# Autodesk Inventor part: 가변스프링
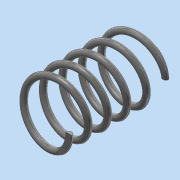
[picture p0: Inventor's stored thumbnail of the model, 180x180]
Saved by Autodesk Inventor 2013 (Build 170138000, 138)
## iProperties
Created: 2017-12
Part Number: 가변스프링
Material: 스테인리스강
Document SubType Name: Modeling
Designer: dgall
Mass: 7.08197 g
Surface Area: 17.7614 cm^2
Volume: 0.876482 cm^3
Density: 8.08 g/cm^3
Author: dgall
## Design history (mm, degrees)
sketch "스케치1"
  geometry: L1 (0, 0)-(0, 28.5); L2 (0, 28.5)-(9, 28.5); L3 (0, 0)-(9, 0); C1 r 1 at (9, 0)
  constraints: 6 end point, 2 parallel, 1 centre point, 1 coincident, 1 perpendicular, 1 vertical
  dimensions: "d0" = 28.5 distance of L1.start L1.end (derived); "d1" = 18 diameter of L3.end L1; "d2" = 2 diameter of C1
feature "코일1" sketch "스케치1" pitch "d3" = 10; turns "d5" = 5; dims "d4" = 28.5 (= d0), "d6" = 0, angle "d7" = 90 deg, angle "d8" = 90 deg, "d9" = 0, "d10" = 0
node "작업 평면1"
node "작업 평면2"
feature "분할1"
feature "분할2"
node "솔리드1"
